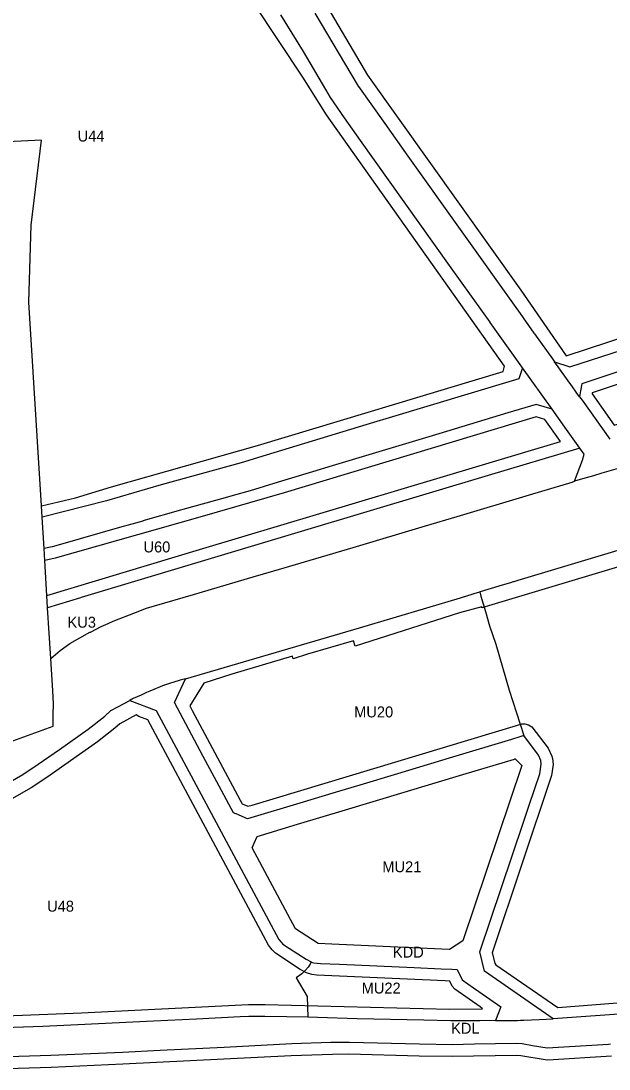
# Model space of a CAD drawing. Extents: x 7428080 to 7432143, y 5545880 to 5549217.
# Drawn here: x 7429340 to 7429639, y 5547123 to 5547655 of the extents above; entities that cross this region are included whole.
import ezdxf

# ---------------------------------------------------------------- set-up
doc = ezdxf.new("R2010")
doc.units = 0
for name, color, linetype in [('CZ_L_linie rozgraniczające tereny o różnym przeznaczeniu oraz różnych warunkach ich zabudowy i zagospodarowania', 7, 'Continuous'), ('CZ_L_maksymalne nieprzekraczalne linie zabudowy', 7, 'Continuous'), ('CZ_L_opisy_linie rozgraniczające tereny o różnym przeznaczeniu oraz różnych warunkach ich zabudowy i zagospodarowania', 7, 'Continuous'), ('info', 7, 'Continuous')]:
    doc.layers.add(name, color=color, linetype=linetype)

msp = doc.modelspace()

# ---------------------------------------------------------------- linework, layer by layer
at = {"layer": 'CZ_L_linie rozgraniczające tereny o różnym przeznaczeniu oraz różnych warunkach ich zabudowy i zagospodarowania'}
for p, q in [((7429483.58, 5547639.4), (7429472.15, 5547658.01)), ((7429489.36, 5547658.82), (7429492.67, 5547653.47)), ((7429492.67, 5547653.47), (7429507.7, 5547628.03)), ((7429483.6, 5547639.36), (7429483.58, 5547639.4)), ((7429494.91, 5547620.17), (7429483.6, 5547639.36)), ((7429507.7, 5547628.03), (7429511.37, 5547621.79)), ((7429511.37, 5547621.79), (7429511.41, 5547621.72)), ((7429511.41, 5547621.72), (7429511.49, 5547621.6)), ((7429511.49, 5547621.6), (7429524.96, 5547602.81)), ((7429497.33, 5547616.06), (7429494.91, 5547620.17)), ((7429504.38, 5547605.73), (7429497.33, 5547616.06)), ((7429512.54, 5547594.28), (7429504.38, 5547605.73)), ((7429524.96, 5547602.81), (7429536.6, 5547586.36)), ((7429557.76, 5547530.82), (7429512.54, 5547594.28)), ((7429536.6, 5547586.36), (7429536.61, 5547586.35)), ((7429536.61, 5547586.35), (7429592.23, 5547508.29)), ((7429574.41, 5547507.43), (7429557.76, 5547530.82)), ((7429578.22, 5547502.07), (7429574.41, 5547507.43)), ((7429592.23, 5547508.29), (7429592.33, 5547508.14)), ((7429592.33, 5547508.14), (7429600.53, 5547496.52)), ((7429578.24, 5547502.06), (7429578.22, 5547502.07)), ((7429578.34, 5547501.93), (7429578.24, 5547502.06)), ((7429578.36, 5547501.9), (7429578.34, 5547501.93)), ((7429588.43, 5547487.7), (7429578.36, 5547501.9)), ((7429600.53, 5547496.52), (7429600.73, 5547496.24)), ((7429600.73, 5547496.24), (7429600.74, 5547496.23)), ((7429600.74, 5547496.23), (7429609.85, 5547483.48)), ((7429618.66, 5547479.36), (7429651.63, 5547490.12)), ((7429593.47, 5547480.64), (7429588.43, 5547487.7)), ((7429609.85, 5547483.48), (7429610.99, 5547481.89)), ((7429594.71, 5547478.91), (7429592.82, 5547473.39)), ((7429594.71, 5547478.91), (7429593.47, 5547480.64)), ((7429609.72, 5547457.88), (7429594.71, 5547478.91)), ((7429612.76, 5547479.41), (7429610.99, 5547481.89)), ((7429610.99, 5547481.89), (7429618.66, 5547479.36)), ((7429613.91, 5547477.81), (7429612.76, 5547479.41)), ((7429620.06, 5547469.2), (7429613.91, 5547477.81)), ((7429656.35, 5547481.37), (7429624.8, 5547470.79)), ((7429589.45, 5547472.38), (7429527.04, 5547453.54)), ((7429592.82, 5547473.39), (7429589.45, 5547472.38)), ((7429621.98, 5547466.52), (7429620.06, 5547469.2)), ((7429623.62, 5547464.23), (7429621.98, 5547466.52)), ((7429624.15, 5547467.18), (7429623.62, 5547464.23)), ((7429624.8, 5547470.79), (7429624.15, 5547467.18)), ((7429623.62, 5547464.23), (7429624.88, 5547462.46)), ((7429624.88, 5547462.46), (7429638.93, 5547442.74)), ((7429587.3, 5547456.06), (7429563.98, 5547449.03)), ((7429601.63, 5547460.39), (7429587.3, 5547456.06)), ((7429609.72, 5547457.88), (7429601.63, 5547460.39)), ((7429616.24, 5547448.74), (7429609.72, 5547457.88)), ((7429519.08, 5547451.14), (7429464.66, 5547434.64)), ((7429527.04, 5547453.54), (7429519.08, 5547451.14)), ((7429552.24, 5547445.48), (7429498.1, 5547429.15)), ((7429552.25, 5547445.49), (7429552.24, 5547445.48)), ((7429563.98, 5547449.03), (7429552.25, 5547445.49)), ((7429623.76, 5547438.18), (7429616.24, 5547448.74)), ((7429464.66, 5547434.64), (7429451.97, 5547430.79)), ((7429623.76, 5547438.18), (7429577.28, 5547424.25)), ((7429625.94, 5547435.13), (7429623.76, 5547438.18)), ((7429625.09, 5547432.02), (7429625.94, 5547435.13)), ((7429451.97, 5547430.79), (7429411.5, 5547419.5)), ((7429621.1, 5547421.34), (7429625.09, 5547432.02)), ((7429488.25, 5547426.14), (7429470.84, 5547420.84)), ((7429577.28, 5547424.25), (7429484.1, 5547396.36)), ((7429498.1, 5547429.15), (7429488.25, 5547426.14)), ((7429630.68, 5547424.17), (7429625.16, 5547422.54)), ((7429634.96, 5547425.43), (7429630.68, 5547424.17)), ((7429644.37, 5547428.21), (7429634.96, 5547425.43)), ((7429411.5, 5547419.5), (7429383.73, 5547411.52)), ((7429470.84, 5547420.84), (7429456.51, 5547416.47)), ((7429598.24, 5547414.51), (7429619.88, 5547420.98)), ((7429619.88, 5547420.98), (7429621.1, 5547421.34)), ((7429625.16, 5547422.54), (7429621.1, 5547421.34)), ((7429447.9, 5547414.08), (7429443.89, 5547412.96)), ((7429456.51, 5547416.47), (7429447.9, 5547414.08)), ((7429561.57, 5547403.53), (7429598.24, 5547414.51)), ((7429383.73, 5547411.52), (7429351.04, 5547403.15)), ((7429443.89, 5547412.96), (7429422.39, 5547406.96)), ((7429421.21, 5547406.63), (7429402.22, 5547401.24)), ((7429422.39, 5547406.96), (7429421.21, 5547406.63)), ((7429545.47, 5547398.71), (7429561.57, 5547403.53)), ((7429390.24, 5547397.84), (7429360.36, 5547389.34)), ((7429396.54, 5547399.63), (7429390.24, 5547397.84)), ((7429402.07, 5547401.2), (7429396.54, 5547399.63)), ((7429402.22, 5547401.24), (7429402.07, 5547401.2)), ((7429508.82, 5547387.76), (7429545.47, 5547398.71)), ((7429484.07, 5547396.35), (7429370.93, 5547362.35)), ((7429484.1, 5547396.36), (7429484.07, 5547396.35)), ((7429356.21, 5547388.16), (7429352.02, 5547387.28)), ((7429360.36, 5547389.34), (7429356.21, 5547388.16)), ((7429473.74, 5547377.43), (7429508.82, 5547387.76)), ((7429648.15, 5547387.7), (7429592.29, 5547370.97)), ((7429458.12, 5547372.87), (7429473.74, 5547377.43)), ((7429427.76, 5547363.99), (7429458.12, 5547372.87)), ((7429592.29, 5547370.97), (7429590.35, 5547370.39)), ((7429582.69, 5547368.1), (7429573.26, 5547365.28)), ((7429585.64, 5547368.98), (7429582.69, 5547368.1)), ((7429588.7, 5547369.9), (7429585.64, 5547368.98)), ((7429589.94, 5547370.27), (7429588.7, 5547369.9)), ((7429590.35, 5547370.39), (7429589.94, 5547370.27)), ((7429370.59, 5547362.25), (7429353.87, 5547357.2)), ((7429370.93, 5547362.35), (7429370.59, 5547362.25)), ((7429407.98, 5547358.17), (7429427.76, 5547363.99)), ((7429512.07, 5547346.96), (7429563.21, 5547362.27)), ((7429563.21, 5547362.27), (7429565.27, 5547362.89)), ((7429565.27, 5547362.89), (7429565.48, 5547362.95)), ((7429565.48, 5547362.95), (7429570.23, 5547364.37)), ((7429570.23, 5547364.37), (7429572.99, 5547365.2)), ((7429573.26, 5547365.28), (7429572.99, 5547365.2)), ((7429572.99, 5547365.2), (7429573.63, 5547363.11)), ((7429573.63, 5547363.11), (7429575.91, 5547355.31)), ((7429387.13, 5547350.36), (7429398.43, 5547354.81)), ((7429398.43, 5547354.81), (7429403.97, 5547356.99)), ((7429403.97, 5547356.99), (7429407.98, 5547358.17)), ((7429575.91, 5547355.31), (7429577.96, 5547348.03)), ((7429384.5, 5547349.23), (7429387.13, 5547350.36)), ((7429365.06, 5547339.08), (7429375.34, 5547344.75)), ((7429375.34, 5547344.75), (7429375.58, 5547344.88)), ((7429375.58, 5547344.88), (7429381.05, 5547347.74)), ((7429381.05, 5547347.74), (7429384.5, 5547349.23)), ((7429423.76, 5547321.16), (7429511.98, 5547346.94)), ((7429511.98, 5547346.94), (7429512.02, 5547346.95)), ((7429511.98, 5547346.94), (7429511.98, 5547346.94)), ((7429512.02, 5547346.95), (7429512.04, 5547346.96)), ((7429512.04, 5547346.96), (7429512.06, 5547346.96)), ((7429512.06, 5547346.96), (7429512.07, 5547346.96)), ((7429577.96, 5547348.03), (7429581.1, 5547338.71)), ((7429360.25, 5547335.48), (7429365.06, 5547339.08)), ((7429355.48, 5547331.48), (7429360.25, 5547335.48)), ((7429581.1, 5547338.71), (7429588.01, 5547315.45)), ((7429355.45, 5547331.45), (7429355.48, 5547331.48)), ((7429412.9, 5547317.89), (7429405.71, 5547314.89)), ((7429413.13, 5547317.99), (7429412.9, 5547317.89)), ((7429416.23, 5547318.92), (7429413.13, 5547317.99)), ((7429420.12, 5547320.09), (7429416.23, 5547318.92)), ((7429418.18, 5547309.07), (7429423.76, 5547321.16)), ((7429420.13, 5547320.09), (7429420.12, 5547320.09)), ((7429421.06, 5547320.37), (7429420.13, 5547320.09)), ((7429423.76, 5547321.16), (7429421.06, 5547320.37)), ((7429401.34, 5547312.91), (7429397.25, 5547311.07)), ((7429404.02, 5547314.12), (7429401.34, 5547312.91)), ((7429405.71, 5547314.89), (7429404.02, 5547314.12)), ((7429588.01, 5547315.45), (7429595.34, 5547292.3)), ((7429385.97, 5547305.08), (7429389.74, 5547307.08)), ((7429389.74, 5547307.08), (7429395.51, 5547310.14)), ((7429396.3, 5547310.56), (7429395.51, 5547310.14)), ((7429395.51, 5547310.14), (7429408.95, 5547305.12)), ((7429396.79, 5547310.82), (7429396.3, 5547310.56)), ((7429397.25, 5547311.07), (7429396.79, 5547310.82)), ((7429432.77, 5547281.77), (7429418.18, 5547309.07)), ((7429374.43, 5547295.59), (7429382.85, 5547302.23)), ((7429382.85, 5547302.23), (7429385.97, 5547305.08)), ((7429408.95, 5547305.12), (7429471.13, 5547188.83)), ((7429359.86, 5547285.32), (7429374.43, 5547295.59)), ((7429593.29, 5547291.74), (7429589.12, 5547290.37)), ((7429595.34, 5547292.3), (7429593.29, 5547291.74)), ((7429602.84, 5547282.39), (7429595.34, 5547292.3)), ((7429589.12, 5547290.37), (7429559.17, 5547281.37)), ((7429349.08, 5547277.8), (7429359.86, 5547285.32)), ((7429438.54, 5547270.98), (7429432.77, 5547281.77)), ((7429559.17, 5547281.37), (7429529.57, 5547272.48)), ((7429564.51, 5547272.54), (7429590.68, 5547280.4)), ((7429590.68, 5547280.4), (7429590.87, 5547280.46)), ((7429590.87, 5547280.46), (7429590.92, 5547280.47)), ((7429590.92, 5547280.47), (7429591, 5547280.5)), ((7429591, 5547280.5), (7429594.3, 5547277.18)), ((7429604.01, 5547279.77), (7429602.84, 5547282.39)), ((7429341.29, 5547272.65), (7429349.08, 5547277.8)), ((7429594.3, 5547277.18), (7429564.48, 5547188.27)), ((7429603.44, 5547273), (7429604.24, 5547277.88)), ((7429604.24, 5547277.88), (7429604.01, 5547279.77)), ((7429327.56, 5547264.7), (7429341.29, 5547272.65)), ((7429448.11, 5547253.09), (7429438.54, 5547270.98)), ((7429504.89, 5547254.62), (7429564.51, 5547272.54)), ((7429529.57, 5547272.48), (7429513.86, 5547267.75)), ((7429598.07, 5547256.97), (7429603.44, 5547273)), ((7429513.86, 5547267.75), (7429498.48, 5547263.13)), ((7429498.48, 5547263.13), (7429483.5, 5547258.63)), ((7429483.5, 5547258.63), (7429455.23, 5547250.13)), ((7429480.64, 5547247.33), (7429504.89, 5547254.62)), ((7429595.02, 5547247.87), (7429598.07, 5547256.97)), ((7429448.13, 5547253.09), (7429448.11, 5547253.09)), ((7429448.17, 5547253.09), (7429448.13, 5547253.09)), ((7429448.6, 5547252.91), (7429448.17, 5547253.09)), ((7429448.87, 5547252.8), (7429448.6, 5547252.91)), ((7429449.47, 5547252.55), (7429448.87, 5547252.8)), ((7429455.23, 5547250.13), (7429449.47, 5547252.55)), ((7429460.06, 5547241.15), (7429480.64, 5547247.33)), ((7429573.11, 5547182.54), (7429595.02, 5547247.87)), ((7429458.6, 5547237.7), (7429460.06, 5547241.15)), ((7429457.6, 5547235.34), (7429458.6, 5547237.7)), ((7429479.51, 5547194.36), (7429457.6, 5547235.34)), ((7429491.04, 5547186.82), (7429479.51, 5547194.36)), ((7429471.13, 5547188.83), (7429472.26, 5547187.47)), ((7429472.26, 5547187.47), (7429473.22, 5547186.58)), ((7429473.22, 5547186.58), (7429476.54, 5547184.35)), ((7429498, 5547186.51), (7429491.04, 5547186.82)), ((7429557.55, 5547183.86), (7429498, 5547186.51)), ((7429564.48, 5547188.27), (7429557.75, 5547183.86)), ((7429476.54, 5547184.35), (7429485.01, 5547178.81)), ((7429557.74, 5547183.85), (7429557.55, 5547183.86)), ((7429557.75, 5547183.86), (7429557.74, 5547183.85)), ((7429575.38, 5547172.72), (7429573.11, 5547182.54)), ((7429485.96, 5547174.77), (7429484.67, 5547173.28)), ((7429485.01, 5547178.81), (7429487.5, 5547177.48)), ((7429487.09, 5547176.33), (7429485.96, 5547174.77)), ((7429487.5, 5547177.48), (7429487.09, 5547176.33)), ((7429487.5, 5547177.48), (7429487.59, 5547177.43)), ((7429487.59, 5547177.43), (7429488.85, 5547177.06)), ((7429488.85, 5547177.06), (7429490.6, 5547176.83)), ((7429490.6, 5547176.83), (7429492.28, 5547176.75)), ((7429492.28, 5547176.75), (7429492.31, 5547176.75)), ((7429492.31, 5547176.75), (7429501.82, 5547176.33)), ((7429501.82, 5547176.33), (7429501.84, 5547176.33)), ((7429501.84, 5547176.33), (7429539.76, 5547174.64)), ((7429539.76, 5547174.64), (7429553.53, 5547174.03)), ((7429553.53, 5547174.03), (7429558.94, 5547173.79)), ((7429482.75, 5547171.37), (7429479.93, 5547169.48)), ((7429479.93, 5547169.48), (7429485.42, 5547160.02)), ((7429484.67, 5547173.28), (7429482.75, 5547171.37)), ((7429558.94, 5547173.79), (7429561.6, 5547173.68)), ((7429561.6, 5547173.68), (7429564.12, 5547168.36)), ((7429610.2, 5547148.7), (7429575.38, 5547172.72)), ((7429564.12, 5547168.36), (7429569.83, 5547164.38)), ((7429569.83, 5547164.38), (7429572.52, 5547162.51)), ((7429485.42, 5547160.02), (7429485.78, 5547149.39)), ((7429572.52, 5547162.51), (7429583.71, 5547154.78)), ((7429583.69, 5547154.73), (7429581.03, 5547147.72)), ((7429583.71, 5547154.78), (7429583.69, 5547154.73)), ((7429695.25, 5547154.73), (7429610.2, 5547148.7)), ((7429429.28, 5547148.44), (7429407.48, 5547147.39)), ((7429451.49, 5547149.59), (7429429.28, 5547148.44)), ((7429455.86, 5547149.82), (7429451.49, 5547149.59)), ((7429464.09, 5547149.87), (7429455.86, 5547149.82)), ((7429475.1, 5547149.62), (7429464.09, 5547149.87)), ((7429485.78, 5547149.39), (7429475.1, 5547149.62)), ((7429490.7, 5547149.28), (7429485.78, 5547149.39)), ((7429510.85, 5547148.69), (7429490.7, 5547149.28)), ((7429544.61, 5547147.87), (7429510.85, 5547148.69)), ((7429558.32, 5547147.54), (7429544.61, 5547147.87)), ((7429573.07, 5547147.67), (7429558.32, 5547147.54)), ((7429581.03, 5547147.72), (7429573.07, 5547147.67)), ((7429581.03, 5547147.72), (7429589.28, 5547147.76)), ((7429589.28, 5547147.76), (7429592.15, 5547147.85)), ((7429592.15, 5547147.85), (7429593.66, 5547147.9)), ((7429593.66, 5547147.9), (7429595.44, 5547147.95)), ((7429595.44, 5547147.95), (7429603.15, 5547148.2)), ((7429603.15, 5547148.2), (7429610.2, 5547148.7)), ((7429351.35, 5547144.79), (7429331.73, 5547144.02)), ((7429369.14, 5547145.58), (7429351.35, 5547144.79)), ((7429407.48, 5547147.39), (7429369.14, 5547145.58)), ((7429391.76, 5547131.59), (7429355.44, 5547129.96)), ((7429410.97, 5547132.54), (7429391.76, 5547131.59)), ((7429443.45, 5547134.14), (7429410.97, 5547132.54)), ((7429477.66, 5547135.87), (7429443.45, 5547134.14)), ((7429497.51, 5547136.54), (7429477.66, 5547135.87)), ((7429506.96, 5547136.67), (7429497.51, 5547136.54)), ((7429542.38, 5547135.69), (7429506.96, 5547136.67)), ((7429559.16, 5547135.5), (7429542.38, 5547135.69)), ((7429570.33, 5547135.7), (7429559.16, 5547135.5)), ((7429591.71, 5547136.02), (7429570.33, 5547135.7)), ((7429594.5, 5547135.91), (7429591.71, 5547136.02)), ((7429599.79, 5547134.91), (7429594.5, 5547135.91)), ((7429607.26, 5547133.66), (7429599.79, 5547134.91)), ((7429638.24, 5547135.65), (7429607.26, 5547133.66)), ((7429639.35, 5547135.73), (7429638.24, 5547135.65)), ((7429355.44, 5547129.96), (7429310.91, 5547128.6))]:
    msp.add_line(p, q, dxfattribs=at)
at = {"layer": 'CZ_L_maksymalne nieprzekraczalne linie zabudowy'}
for points in [[(7429350.68, 5547408.98), (7429368.07, 5547412.95), (7429386.29, 5547418.49), (7429460.25, 5547439.49), (7429584.94, 5547477.06), (7429585.5, 5547479.83), (7429495.31, 5547607.21), (7429483.29, 5547626.42), (7429422.21, 5547718.65), (7429357.55, 5547821.09), (7429348.01, 5547837.72), (7429327.54, 5547851.7), (7429222.85, 5547846.55)], [(7429432.98, 5547762.57), (7429443.33, 5547745.41), (7429497.66, 5547658.67), (7429516.16, 5547627.33), (7429593.82, 5547518.3), (7429616.89, 5547485.09), (7429649.28, 5547495.66), (7429697.79, 5547521.36), (7429709.74, 5547525.83), (7429768.93, 5547549.39), (7429774.37, 5547552.18), (7429874.72, 5547592.88)], [(7429712.49, 5547503.45), (7429694.08, 5547494.43), (7429658.71, 5547475.84), (7429630.07, 5547466.23), (7429629.97, 5547465.65), (7429641.26, 5547449.8), (7429757.88, 5547484.66), (7429771.7, 5547489.24), (7429905.93, 5547537.32), (7429926.05, 5547548.72)], [(7429353.49, 5547363.35), (7429430.84, 5547386.71), (7429614.04, 5547441.49), (7429606.01, 5547452.75), (7429601.61, 5547454.11), (7429473.79, 5547415.47), (7429431.12, 5547403.17), (7429357.66, 5547382.34), (7429352.39, 5547381.24)], [(7429650.23, 5547379.97), (7429574.15, 5547357.19), (7429574.08, 5547357.61), (7429562.7, 5547354.64), (7429509.75, 5547337.72), (7429508.96, 5547340.33), (7429485.68, 5547333.59), (7429478.46, 5547331.21), (7429478.03, 5547332.65), (7429447.22, 5547323.43), (7429433.09, 5547318.99), (7429425.96, 5547307.49), (7429427.11, 5547305.08), (7429451.44, 5547259.58), (7429452.58, 5547257.75), (7429455.4, 5547256.57), (7429457.52, 5547257.09), (7429591.7, 5547297.52), (7429594.29, 5547298.21), (7429595.87, 5547298.27), (7429597.77, 5547297.79), (7429599.4, 5547296.71), (7429607.69, 5547285.92), (7429609.61, 5547281.93), (7429609.92, 5547280.78), (7429610.24, 5547277.74), (7429609.36, 5547272.03), (7429579.38, 5547182.04), (7429580.59, 5547176.82), (7429581.24, 5547175.97), (7429612.64, 5547154.3)], [(7429332.53, 5547150.06), (7429370.96, 5547151.68), (7429455.81, 5547155.82), (7429464.23, 5547155.87), (7429490.83, 5547155.28), (7429557.63, 5547153.56), (7429574.39, 5547153.68), (7429573.15, 5547154.78), (7429560.35, 5547163.69), (7429559.05, 5547165.15), (7429557.79, 5547167.71), (7429555.52, 5547167.93), (7429490.32, 5547170.84), (7429487.92, 5547171.14), (7429485.18, 5547171.94), (7429481.89, 5547173.69), (7429469.44, 5547181.93), (7429467.67, 5547183.61), (7429465.86, 5547185.96), (7429404.62, 5547300.34), (7429400.12, 5547302.02), (7429398.7, 5547302.78), (7429390.47, 5547298.35), (7429387.97, 5547296.09), (7429379.14, 5547289.13), (7429353.51, 5547271.14), (7429345.53, 5547265.87), (7429330.95, 5547257.45)], [(7429612.64, 5547154.3), (7429692.42, 5547160.54)], [(7429639.87, 5547129.69), (7429607.51, 5547127.67), (7429606.27, 5547127.74), (7429593.84, 5547129.92), (7429591.66, 5547130.02), (7429559.09, 5547129.5), (7429542.24, 5547129.69), (7429506.61, 5547130.67), (7429498.34, 5547130.55), (7429477.31, 5547129.85), (7429392.03, 5547125.59), (7429355.68, 5547123.96), (7429311.09, 5547122.6)]]:
    msp.add_lwpolyline(points, dxfattribs=at)
at = {"layer": 'info'}
msp.add_line((7429356.86, 5547308.44), (7429356.46, 5547315), dxfattribs=at)
for points in [[(7429356.46, 5547315), (7429355.45, 5547331.45), (7429353.87, 5547357.2), (7429353.49, 5547363.35), (7429352.39, 5547381.24), (7429352.02, 5547387.28), (7429351.04, 5547403.15), (7429350.68, 5547408.98), (7429344.33, 5547512.3), (7429345.51, 5547551.35), (7429350.77, 5547594.37), (7429232.96, 5547588.73)], [(7429169.2, 5547233.58), (7429261.57, 5547262.53), (7429356.72, 5547297.08), (7429356.72, 5547302.84), (7429356.86, 5547308.44)]]:
    msp.add_lwpolyline(points, dxfattribs=at)

# ---------------------------------------------------------------- texts
at = {"layer": 'CZ_L_opisy_linie rozgraniczające tereny o różnym przeznaczeniu oraz różnych warunkach ich zabudowy i zagospodarowania'}
for s, p in [('U44', (7429369.09, 5547593.73)), ('U60', (7429402.47, 5547385.27)), ('KU3', (7429363.92, 5547347.07)), ('MU20', (7429509.32, 5547301.56)), ('MU21', (7429523.6, 5547222.99)), ('U48', (7429353.59, 5547202.98)), ('KDD', (7429528.97, 5547179.66)), ('MU22', (7429513.13, 5547161.45)), ('KDL', (7429558.5, 5547141.07))]:
    msp.add_text(s, height=5.549, dxfattribs=at).set_placement(p)

doc.saveas('drawing.dxf')
